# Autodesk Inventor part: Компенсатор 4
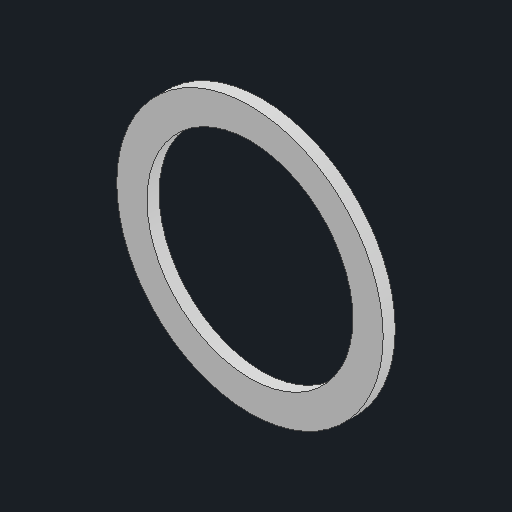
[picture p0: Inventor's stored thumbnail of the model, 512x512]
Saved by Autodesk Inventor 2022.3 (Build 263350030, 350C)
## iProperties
Created: 2020-09
Part Number: Компенсатор 4
Material: Типовые
Document SubType Name: Modeling
Designer: Карташов
Density: 1 g/cm^3
Appearance: По умолчанию
Title: D:\мои документы\Ирина\_WorldSkills\2020_09 ФНЧ\Module A\Участникам\GIVEN\Компенсатор 4.stp
Author: Дом
Sending System: Autodesk Inventor 2021
Preprocessor: ST-DEVELOPER v18.1
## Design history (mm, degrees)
feature "Твердое тело2"
node "Твердое тело1"
